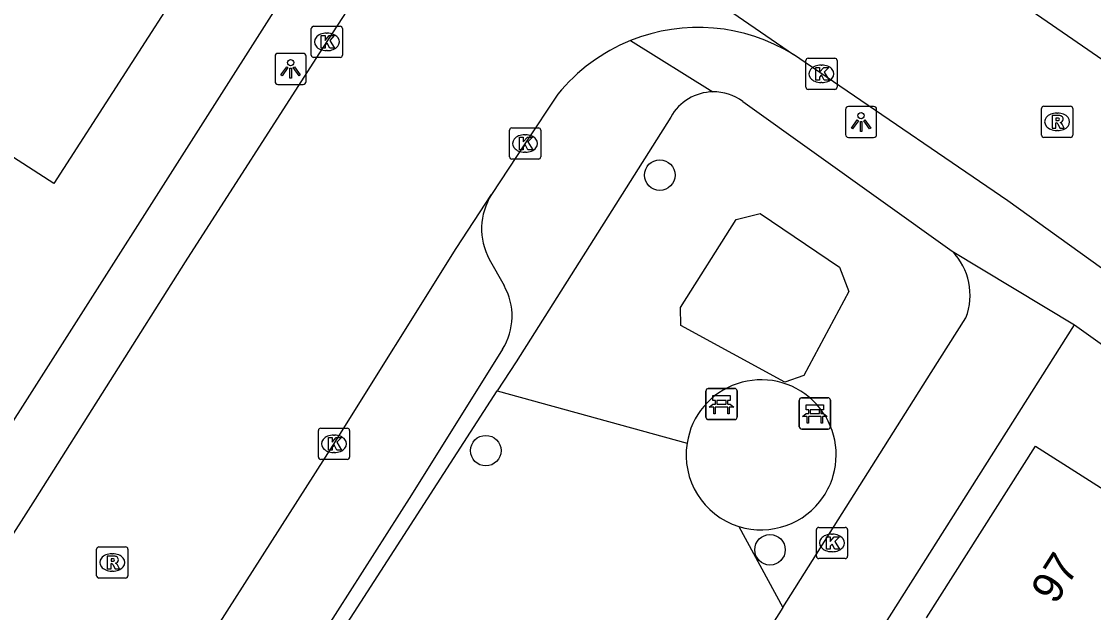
# Model space of a CAD drawing. Extents: x 159040 to 160094, y 381214 to 382518.
# Drawn here: x 159351.38 to 159385.76, y 381864.25 to 381883.21 of the extents above; entities that cross this region are included whole.
import ezdxf

# ---------------------------------------------------------------- set-up
doc = ezdxf.new("R2010")
doc.units = 0
for name, color, linetype in [('IMGEO_Bank', 7, 'Continuous'), ('IMGEO_Boom', 7, 'Continuous'), ('IMGEO_Groenvoorziening', 7, 'Continuous'), ('IMGEO_Kolk', 7, 'Continuous'), ('IMGEO_Lichtpunt', 7, 'Continuous'), ('IMGEO_Pand', 7, 'Continuous'), ('IMGEO_Pand_nummerreeks', 7, 'Continuous'), ('IMGEO_Rijbaan_lokaal_open', 7, 'Continuous'), ('IMGEO_Rioolput', 7, 'Continuous'), ('IMGEO_Voetpad_halfverhard', 7, 'Continuous'), ('IMGEO_Voetpad_open', 7, 'Continuous')]:
    doc.layers.add(name, color=color, linetype=linetype)

msp = doc.modelspace()

# ---------------------------------------------------------------- linework, layer by layer
at = {"layer": 'IMGEO_Bank'}
for p, q in [((159373.328, 381870.51), (159373.328, 381871.351)), ((159373.328, 381871.351), (159373.328, 381870.51)), ((159373.403, 381871.435), (159374.244, 381871.435)), ((159374.244, 381871.435), (159373.403, 381871.435)), ((159374.328, 381871.36), (159374.328, 381870.519)), ((159374.328, 381870.519), (159374.328, 381871.36)), ((159374.025, 381870.833), (159373.632, 381870.833)), ((159373.637, 381870.941), (159373.637, 381871.047)), ((159373.681, 381871.047), (159373.681, 381870.941)), ((159373.969, 381871.053), (159373.687, 381871.053)), ((159373.687, 381870.935), (159373.969, 381870.935)), ((159373.975, 381870.941), (159373.975, 381871.047)), ((159374.019, 381871.047), (159374.019, 381870.941)), ((159376.32, 381870.209), (159376.32, 381871.05)), ((159376.32, 381871.05), (159376.32, 381870.209)), ((159376.395, 381871.134), (159377.236, 381871.134)), ((159377.236, 381871.134), (159376.395, 381871.134)), ((159377.32, 381871.059), (159377.32, 381870.218)), ((159377.32, 381870.218), (159377.32, 381871.059)), ((159377.017, 381870.532), (159376.624, 381870.532)), ((159376.629, 381870.64), (159376.629, 381870.746)), ((159376.673, 381870.746), (159376.673, 381870.64)), ((159376.961, 381870.752), (159376.679, 381870.752)), ((159376.679, 381870.634), (159376.961, 381870.634)), ((159376.967, 381870.64), (159376.967, 381870.746)), ((159377.011, 381870.746), (159377.011, 381870.64)), ((159374.253, 381870.435), (159373.412, 381870.435)), ((159373.412, 381870.435), (159374.253, 381870.435)), ((159377.245, 381870.134), (159376.404, 381870.134)), ((159376.404, 381870.134), (159377.245, 381870.134))]:
    msp.add_line(p, q, dxfattribs=at)
for points in [[(159373.631, 381871.053), (159373.545, 381871.053), (159373.545, 381871.214), (159374.108, 381871.214), (159374.108, 381871.053), (159374.025, 381871.053)], [(159373.575, 381870.833), (159373.433, 381870.833), (159373.545, 381870.935), (159373.631, 381870.935)], [(159373.625, 381870.826), (159373.625, 381870.619), (159373.582, 381870.619), (159373.582, 381870.826)], [(159374.025, 381870.935), (159374.108, 381870.935), (159374.22, 381870.833), (159374.081, 381870.833)], [(159374.075, 381870.826), (159374.075, 381870.619), (159374.031, 381870.619), (159374.031, 381870.826)], [(159376.623, 381870.752), (159376.537, 381870.752), (159376.537, 381870.913), (159377.1, 381870.913), (159377.1, 381870.752), (159377.017, 381870.752)], [(159376.567, 381870.532), (159376.425, 381870.532), (159376.537, 381870.634), (159376.623, 381870.634)], [(159376.617, 381870.525), (159376.617, 381870.318), (159376.574, 381870.318), (159376.574, 381870.525)], [(159377.017, 381870.634), (159377.1, 381870.634), (159377.212, 381870.532), (159377.073, 381870.532)], [(159377.067, 381870.525), (159377.067, 381870.318), (159377.023, 381870.318), (159377.023, 381870.525)]]:
    msp.add_lwpolyline(points, dxfattribs=at)
for centre, radius, start, end in [((159373.406, 381871.357), 0.0779, 92.4484, 184.2845), ((159373.406, 381871.357), 0.0779, 92.4484, 184.2845), ((159374.25, 381871.357), 0.0779, 2.4484, 94.2845), ((159374.25, 381871.357), 0.0779, 2.4484, 94.2845), ((159373.575, 381870.826), 0.00671, 2.8957, 87.1043), ((159373.632, 381870.826), 0.00671, 92.8957, 177.1043), ((159373.63, 381871.046), 0.00671, 2.8957, 87.1043), ((159373.63, 381870.942), 0.00671, 272.8957, 357.1043), ((159373.687, 381871.046), 0.00671, 92.8957, 177.1043), ((159373.687, 381870.942), 0.00671, 182.8957, 267.1043), ((159373.969, 381871.046), 0.00671, 2.8957, 87.1043), ((159373.969, 381870.942), 0.00671, 272.8957, 357.1043), ((159374.026, 381871.046), 0.00671, 92.8957, 177.1043), ((159374.026, 381870.942), 0.00671, 182.8957, 267.1043), ((159374.024, 381870.826), 0.00671, 2.8957, 87.1043), ((159374.081, 381870.826), 0.00671, 92.8957, 177.1043), ((159376.398, 381871.056), 0.0779, 92.4484, 184.2845), ((159376.398, 381871.056), 0.0779, 92.4484, 184.2845), ((159377.242, 381871.056), 0.0779, 2.4484, 94.2845), ((159377.242, 381871.056), 0.0779, 2.4484, 94.2845), ((159373.406, 381870.513), 0.0779, 182.4484, 274.2845), ((159373.406, 381870.513), 0.0779, 182.4484, 274.2845), ((159374.25, 381870.513), 0.0779, 272.4484, 4.2845), ((159374.25, 381870.513), 0.0779, 272.4484, 4.2845), ((159376.567, 381870.525), 0.00671, 2.8957, 87.1043), ((159376.624, 381870.525), 0.00671, 92.8957, 177.1043), ((159376.622, 381870.745), 0.00671, 2.8957, 87.1043), ((159376.622, 381870.641), 0.00671, 272.8957, 357.1043), ((159376.679, 381870.745), 0.00671, 92.8957, 177.1043), ((159376.679, 381870.641), 0.00671, 182.8957, 267.1043), ((159376.961, 381870.745), 0.00671, 2.8957, 87.1043), ((159376.961, 381870.641), 0.00671, 272.8957, 357.1043), ((159377.018, 381870.745), 0.00671, 92.8957, 177.1043), ((159377.018, 381870.641), 0.00671, 182.8957, 267.1043), ((159377.016, 381870.525), 0.00671, 2.8957, 87.1043), ((159377.073, 381870.525), 0.00671, 92.8957, 177.1043), ((159376.398, 381870.212), 0.0779, 182.4484, 274.2845), ((159376.398, 381870.212), 0.0779, 182.4484, 274.2845), ((159377.242, 381870.212), 0.0779, 272.4484, 4.2845), ((159377.242, 381870.212), 0.0779, 272.4484, 4.2845)]:
    msp.add_arc(centre, radius, start, end, dxfattribs=at)
at = {"layer": 'IMGEO_Boom'}
for centre in [(159371.847, 381878.277), (159366.267, 381869.441), (159375.382, 381866.261)]:
    msp.add_circle(centre, 0.489, dxfattribs=at)
at = {"layer": 'IMGEO_Groenvoorziening'}
for points in [[(159366.633, 381871.354), (159372.721, 381869.68)], [(159374.378, 381867.01), (159375.795, 381864.415)]]:
    msp.add_lwpolyline(points, dxfattribs=at)
at = {"layer": 'IMGEO_Kolk'}
for p, q in [((159360.671, 381882.123), (159360.671, 381882.975)), ((159360.746, 381883.049), (159361.598, 381883.049)), ((159361.672, 381882.975), (159361.672, 381882.123)), ((159361.159, 381882.829), (159361.184, 381882.829)), ((159361.182, 381882.269), (159361.157, 381882.269)), ((159361.598, 381882.049), (159360.746, 381882.049)), ((159376.531, 381881.1), (159376.531, 381881.952)), ((159376.606, 381882.026), (159377.458, 381882.026)), ((159377.532, 381881.952), (159377.532, 381881.1)), ((159377.019, 381881.806), (159377.044, 381881.806)), ((159377.042, 381881.246), (159377.017, 381881.246)), ((159377.458, 381881.026), (159376.606, 381881.026)), ((159367.102, 381879.791), (159367.954, 381879.791)), ((159367.027, 381878.865), (159367.027, 381879.717)), ((159367.515, 381879.571), (159367.54, 381879.571)), ((159368.028, 381879.717), (159368.028, 381878.865)), ((159367.954, 381878.791), (159367.102, 381878.791)), ((159367.538, 381879.011), (159367.513, 381879.011)), ((159360.974, 381870.159), (159361.826, 381870.159)), ((159360.899, 381869.233), (159360.899, 381870.085)), ((159361.387, 381869.939), (159361.412, 381869.939)), ((159361.9, 381870.085), (159361.9, 381869.233)), ((159361.826, 381869.159), (159360.974, 381869.159)), ((159361.41, 381869.379), (159361.385, 381869.379)), ((159376.871, 381866.054), (159376.871, 381866.906)), ((159376.946, 381866.98), (159377.798, 381866.98)), ((159377.359, 381866.76), (159377.384, 381866.76)), ((159377.872, 381866.906), (159377.872, 381866.054)), ((159377.382, 381866.2), (159377.357, 381866.2)), ((159377.798, 381865.98), (159376.946, 381865.98))]:
    msp.add_line(p, q, dxfattribs=at)
for points in [[(159360.671, 381882.123), (159360.671, 381882.975)], [(159360.746, 381883.049), (159361.598, 381883.049)], [(159361.672, 381882.975), (159361.672, 381882.123)], [(159360.992, 381882.749), (159361.115, 381882.749), (159361.115, 381882.598), (159361.245, 381882.749), (159361.409, 381882.749), (159361.263, 381882.598), (159361.416, 381882.349), (159361.264, 381882.349), (159361.179, 381882.513), (159361.115, 381882.446), (159361.115, 381882.349), (159360.992, 381882.349), (159360.992, 381882.749)], [(159361.598, 381882.049), (159360.746, 381882.049)], [(159376.531, 381881.1), (159376.531, 381881.952)], [(159376.606, 381882.026), (159377.458, 381882.026)], [(159377.532, 381881.952), (159377.532, 381881.1)], [(159376.852, 381881.726), (159376.975, 381881.726), (159376.975, 381881.575), (159377.105, 381881.726), (159377.269, 381881.726), (159377.123, 381881.575), (159377.276, 381881.326), (159377.124, 381881.326), (159377.039, 381881.49), (159376.975, 381881.423), (159376.975, 381881.326), (159376.852, 381881.326), (159376.852, 381881.726)], [(159377.458, 381881.026), (159376.606, 381881.026)], [(159367.102, 381879.791), (159367.954, 381879.791)], [(159367.027, 381878.865), (159367.027, 381879.717)], [(159367.348, 381879.491), (159367.471, 381879.491), (159367.471, 381879.34), (159367.601, 381879.491), (159367.765, 381879.491), (159367.619, 381879.34), (159367.772, 381879.091), (159367.62, 381879.091), (159367.535, 381879.255), (159367.471, 381879.188), (159367.471, 381879.091), (159367.348, 381879.091), (159367.348, 381879.491)], [(159368.028, 381879.717), (159368.028, 381878.865)], [(159367.954, 381878.791), (159367.102, 381878.791)], [(159360.974, 381870.159), (159361.826, 381870.159)], [(159360.899, 381869.233), (159360.899, 381870.085)], [(159361.22, 381869.859), (159361.343, 381869.859), (159361.343, 381869.708), (159361.473, 381869.859), (159361.637, 381869.859), (159361.491, 381869.708), (159361.644, 381869.459), (159361.492, 381869.459), (159361.407, 381869.623), (159361.343, 381869.556), (159361.343, 381869.459), (159361.22, 381869.459), (159361.22, 381869.859)], [(159361.9, 381870.085), (159361.9, 381869.233)], [(159361.826, 381869.159), (159360.974, 381869.159)], [(159376.871, 381866.054), (159376.871, 381866.906)], [(159376.946, 381866.98), (159377.798, 381866.98)], [(159377.872, 381866.906), (159377.872, 381866.054)], [(159377.192, 381866.68), (159377.315, 381866.68), (159377.315, 381866.529), (159377.445, 381866.68), (159377.609, 381866.68), (159377.463, 381866.529), (159377.616, 381866.28), (159377.464, 381866.28), (159377.379, 381866.444), (159377.315, 381866.377), (159377.315, 381866.28), (159377.192, 381866.28), (159377.192, 381866.68)], [(159377.798, 381865.98), (159376.946, 381865.98)]]:
    msp.add_lwpolyline(points, dxfattribs=at)
for centre, start, end in [((159360.748, 381882.973), 91.552, 178.448), ((159360.748, 381882.973), 91.552, 178.448), ((159361.596, 381882.973), 1.552, 88.448), ((159361.596, 381882.973), 1.552, 88.448), ((159360.748, 381882.125), 181.552, 268.448), ((159360.748, 381882.125), 181.552, 268.448), ((159361.596, 381882.125), 271.552, 358.448), ((159361.596, 381882.125), 271.552, 358.448), ((159376.608, 381881.95), 91.552, 178.448), ((159376.608, 381881.95), 91.552, 178.448), ((159377.456, 381881.95), 1.552, 88.448), ((159377.456, 381881.95), 1.552, 88.448), ((159376.608, 381881.102), 181.552, 268.448), ((159376.608, 381881.102), 181.552, 268.448), ((159377.456, 381881.102), 271.552, 358.448), ((159377.456, 381881.102), 271.552, 358.448), ((159367.104, 381879.715), 91.552, 178.448), ((159367.104, 381879.715), 91.552, 178.448), ((159367.952, 381879.715), 1.552, 88.448), ((159367.952, 381879.715), 1.552, 88.448), ((159367.104, 381878.867), 181.552, 268.448), ((159367.104, 381878.867), 181.552, 268.448), ((159367.952, 381878.867), 271.552, 358.448), ((159367.952, 381878.867), 271.552, 358.448), ((159360.976, 381870.083), 91.552, 178.448), ((159360.976, 381870.083), 91.552, 178.448), ((159361.824, 381870.083), 1.552, 88.448), ((159361.824, 381870.083), 1.552, 88.448), ((159360.976, 381869.235), 181.552, 268.448), ((159360.976, 381869.235), 181.552, 268.448), ((159361.824, 381869.235), 271.552, 358.448), ((159361.824, 381869.235), 271.552, 358.448), ((159376.948, 381866.904), 91.552, 178.448), ((159376.948, 381866.904), 91.552, 178.448), ((159377.796, 381866.904), 1.552, 88.448), ((159377.796, 381866.904), 1.552, 88.448), ((159376.948, 381866.056), 181.552, 268.448), ((159376.948, 381866.056), 181.552, 268.448), ((159377.796, 381866.056), 271.552, 358.448), ((159377.796, 381866.056), 271.552, 358.448)]:
    msp.add_arc(centre, 0.0765, start, end, dxfattribs=at)
for centre, major_axis, ratio, start_param, end_param in [((159361.158, 381882.549), (-0.387, 0.002), 0.722429, 4.712389, 7.853982), ((159361.183, 381882.549), (-0.39, 0.002), 0.717154, 1.570796, 4.712389), ((159377.018, 381881.526), (-0.387, 0.002), 0.722429, 4.712389, 7.853982), ((159377.043, 381881.526), (-0.39, 0.002), 0.717154, 1.570796, 4.712389), ((159367.514, 381879.291), (-0.387, 0.002), 0.722429, 4.712389, 7.853982), ((159367.539, 381879.291), (-0.39, 0.002), 0.717154, 1.570796, 4.712389), ((159361.386, 381869.659), (-0.387, 0.002), 0.722429, 4.712389, 7.853982), ((159361.411, 381869.659), (-0.39, 0.002), 0.717154, 1.570796, 4.712389), ((159377.358, 381866.48), (-0.387, 0.002), 0.722429, 4.712389, 7.853982), ((159377.383, 381866.48), (-0.39, 0.002), 0.717154, 1.570796, 4.712389)]:
    msp.add_ellipse(centre, major_axis=major_axis, ratio=ratio, start_param=start_param, end_param=end_param, dxfattribs=at)
at = {"layer": 'IMGEO_Lichtpunt'}
for p, q in [((159360.41, 381882.182), (159359.602, 381882.182)), ((159360.41, 381882.182), (159359.602, 381882.182)), ((159359.508, 381882.087), (159359.508, 381881.28)), ((159359.508, 381882.087), (159359.508, 381881.28)), ((159360.504, 381881.28), (159360.504, 381882.087)), ((159360.504, 381881.28), (159360.504, 381882.087)), ((159359.602, 381881.186), (159360.41, 381881.186)), ((159359.602, 381881.186), (159360.41, 381881.186)), ((159378.707, 381880.479), (159377.899, 381880.479)), ((159378.707, 381880.479), (159377.899, 381880.479)), ((159377.805, 381880.384), (159377.805, 381879.577)), ((159377.805, 381880.384), (159377.805, 381879.577)), ((159378.801, 381879.577), (159378.801, 381880.384)), ((159378.801, 381879.577), (159378.801, 381880.384)), ((159377.899, 381879.483), (159378.707, 381879.483)), ((159377.899, 381879.483), (159378.707, 381879.483))]:
    msp.add_line(p, q, dxfattribs=at)
for points in [[(159359.882, 381881.751), (159359.921, 381881.723), (159359.733, 381881.461), (159359.695, 381881.488), (159359.882, 381881.751)], [(159359.984, 381881.703), (159360.031, 381881.703), (159360.031, 381881.381), (159359.984, 381881.381), (159359.984, 381881.703)], [(159360.094, 381881.723), (159360.132, 381881.75), (159360.319, 381881.488), (159360.28, 381881.46), (159360.094, 381881.723)], [(159378.179, 381880.048), (159378.218, 381880.02), (159378.03, 381879.758), (159377.992, 381879.785), (159378.179, 381880.048)], [(159378.281, 381880), (159378.328, 381880), (159378.328, 381879.678), (159378.281, 381879.678), (159378.281, 381880)], [(159378.391, 381880.02), (159378.429, 381880.047), (159378.616, 381879.785), (159378.577, 381879.757), (159378.391, 381880.02)]]:
    msp.add_lwpolyline(points, dxfattribs=at)
for centre in [(159360.007, 381881.885), (159378.304, 381880.182)]:
    msp.add_circle(centre, 0.0994, dxfattribs=at)
for centre, start, end in [((159359.602, 381882.087), 90, 180), ((159359.602, 381882.087), 90, 180), ((159360.41, 381882.087), 0, 90), ((159360.41, 381882.087), 0, 90), ((159359.602, 381881.28), 180, 270), ((159359.602, 381881.28), 180, 270), ((159360.41, 381881.28), 270, 0), ((159360.41, 381881.28), 270, 360), ((159377.899, 381880.384), 90, 180), ((159377.899, 381880.384), 90, 180), ((159378.707, 381880.384), 0, 90), ((159378.707, 381880.384), 0, 90), ((159377.899, 381879.577), 180, 270), ((159377.899, 381879.577), 180, 270), ((159378.707, 381879.577), 270, 0), ((159378.707, 381879.577), 270, 360)]:
    msp.add_arc(centre, 0.0946, start, end, dxfattribs=at)
at = {"layer": 'IMGEO_Pand'}
for points in [[(159351.372, 381888.315), (159356.797, 381884.82), (159352.409, 381878.007), (159346.983, 381881.502)], [(159380.405, 381864.08), (159383.895, 381869.579), (159391.026, 381865.053), (159388.347, 381860.832), (159387.536, 381859.554)]]:
    msp.add_lwpolyline(points, dxfattribs=at)
at = {"layer": 'IMGEO_Rijbaan_lokaal_open'}
for points in [[(159356.898, 381904.755), (159359.228, 381902.824), (159361.803, 381900.713), (159364.908, 381898.01), (159368.906, 381894.441), (159371.682, 381891.995), (159372.607, 381891.419), (159374.914, 381889.793), (159378.123, 381887.473), (159378.766, 381887.027), (159382.491, 381884.442), (159394.639, 381876.061), (159401.266, 381871.522), (159409.164, 381865.996), (159418.724, 381859.338), (159420.402, 381857.938), (159424.695, 381854.911)], [(159362.316, 381891.65), (159376.136, 381882.142)], [(159336.942, 381844.497), (159338.933, 381847.625), (159344.796, 381856.852), (159346.625, 381859.725), (159351.829, 381867.879), (159356.637, 381875.498), (159360.926, 381882.168), (159362.58, 381884.718)], [(159421.598, 381850.302), (159417.059, 381853.43), (159413.89, 381855.955), (159406.023, 381861.421), (159397.966, 381866.975), (159388.94, 381873.188), (159383.005, 381877.455), (159377.184, 381881.424), (159376.136, 381882.142)], [(159368.58, 381880.87), (159367.537, 381879.308), (159366.451, 381877.655)], [(159338.189, 381833.159), (159342.307, 381839.702), (159347.915, 381848.544), (159353.758, 381857.696), (159361.37, 381869.614), (159365.312, 381875.921), (159366.451, 381877.655)]]:
    msp.add_lwpolyline(points, dxfattribs=at)
for centre, radius, start, end in [((159373.079, 381877.215), 5.799, 58.1849, 111.9995), ((159373.089, 381877.206), 5.81, 112.0631, 140.9086)]:
    msp.add_arc(centre, radius, start, end, dxfattribs=at)
at = {"layer": 'IMGEO_Rioolput'}
for p, q in [((159384.166, 381880.487), (159385.018, 381880.487)), ((159384.091, 381879.561), (159384.091, 381880.413)), ((159384.579, 381880.267), (159384.604, 381880.267)), ((159385.092, 381880.413), (159385.092, 381879.561)), ((159385.018, 381879.487), (159384.166, 381879.487)), ((159384.602, 381879.707), (159384.577, 381879.707)), ((159353.862, 381866.355), (159354.714, 381866.355)), ((159353.787, 381865.429), (159353.787, 381866.281)), ((159354.275, 381866.135), (159354.3, 381866.135)), ((159354.788, 381866.281), (159354.788, 381865.429)), ((159354.714, 381865.355), (159353.862, 381865.355)), ((159354.298, 381865.575), (159354.273, 381865.575))]:
    msp.add_line(p, q, dxfattribs=at)
for points in [[(159384.166, 381880.487), (159385.018, 381880.487)], [(159384.091, 381879.561), (159384.091, 381880.413)], [(159384.68, 381880.185), (159384.428, 381880.187), (159384.428, 381879.787)], [(159384.606, 381880.106), (159384.552, 381880.106), (159384.552, 381880.025)], [(159385.092, 381880.413), (159385.092, 381879.561)], [(159384.428, 381879.787), (159384.552, 381879.787), (159384.552, 381879.949), (159384.563, 381879.949)], [(159384.552, 381880.025), (159384.604, 381880.025)], [(159384.61, 381879.92), (159384.681, 381879.787), (159384.821, 381879.787), (159384.756, 381879.913)], [(159385.018, 381879.487), (159384.166, 381879.487)], [(159353.862, 381866.355), (159354.714, 381866.355)], [(159353.787, 381865.429), (159353.787, 381866.281)], [(159354.376, 381866.053), (159354.124, 381866.055), (159354.124, 381865.655)], [(159354.788, 381866.281), (159354.788, 381865.429)], [(159354.124, 381865.655), (159354.248, 381865.655), (159354.248, 381865.817), (159354.259, 381865.817)], [(159354.302, 381865.974), (159354.248, 381865.974), (159354.248, 381865.893)], [(159354.248, 381865.893), (159354.3, 381865.893)], [(159354.306, 381865.788), (159354.377, 381865.655), (159354.517, 381865.655), (159354.452, 381865.781)], [(159354.714, 381865.355), (159353.862, 381865.355)]]:
    msp.add_lwpolyline(points, dxfattribs=at)
for centre, radius, start, end in [((159384.168, 381880.411), 0.0765, 91.552, 178.448), ((159384.168, 381880.411), 0.0765, 91.552, 178.448), ((159385.016, 381880.411), 0.0765, 1.552, 88.448), ((159385.016, 381880.411), 0.0765, 1.552, 88.448), ((159384.612, 381880.01), 0.0964, 77.0061, 93.1865), ((159384.626, 381880.067), 0.0378, 276.6634, 79.6772), ((159384.679, 381880.075), 0.109, 350.3612, 89.416), ((159384.562, 381879.896), 0.0533, 26.0293, 88.6989), ((159384.588, 381880.214), 0.19, 274.7715, 282.9687), ((159384.677, 381880.075), 0.112, 277.5842, 350.9817), ((159384.661, 381879.86), 0.108, 29.5134, 73.7905), ((159384.168, 381879.563), 0.0765, 181.552, 268.448), ((159384.168, 381879.563), 0.0765, 181.552, 268.448), ((159385.016, 381879.563), 0.0765, 271.552, 358.448), ((159385.016, 381879.563), 0.0765, 271.552, 358.448), ((159353.864, 381866.279), 0.0765, 91.552, 178.448), ((159353.864, 381866.279), 0.0765, 91.552, 178.448), ((159354.712, 381866.279), 0.0765, 1.552, 88.448), ((159354.712, 381866.279), 0.0765, 1.552, 88.448), ((159354.375, 381865.943), 0.109, 350.3612, 89.416), ((159354.258, 381865.764), 0.0533, 26.0293, 88.6989), ((159354.284, 381866.082), 0.19, 274.7715, 282.9687), ((159354.308, 381865.878), 0.0964, 77.0061, 93.1865), ((159354.322, 381865.935), 0.0378, 276.6634, 79.6772), ((159354.373, 381865.943), 0.112, 277.5842, 350.9817), ((159354.357, 381865.728), 0.108, 29.5134, 73.7905), ((159353.864, 381865.431), 0.0765, 181.552, 268.448), ((159353.864, 381865.431), 0.0765, 181.552, 268.448), ((159354.712, 381865.431), 0.0765, 271.552, 358.448), ((159354.712, 381865.431), 0.0765, 271.552, 358.448)]:
    msp.add_arc(centre, radius, start, end, dxfattribs=at)
for centre, major_axis, ratio, start_param, end_param in [((159384.578, 381879.987), (-0.387, 0.002), 0.722429, 4.712389, 7.853982), ((159384.603, 381879.987), (-0.39, 0.002), 0.717154, 1.570796, 4.712389), ((159354.274, 381865.855), (-0.387, 0.002), 0.722429, 4.712389, 7.853982), ((159354.299, 381865.855), (-0.39, 0.002), 0.717154, 1.570796, 4.712389)]:
    msp.add_ellipse(centre, major_axis=major_axis, ratio=ratio, start_param=start_param, end_param=end_param, dxfattribs=at)
at = {"layer": 'IMGEO_Voetpad_halfverhard'}
msp.add_lwpolyline([(159377.606, 381875.321), (159377.907, 381874.539), (159376.47, 381871.851), (159375.858, 381871.638), (159372.524, 381873.451), (159372.509, 381874.026), (159374.292, 381876.849), (159375.062, 381877.046), (159377.606, 381875.321)], dxfattribs=at)
for centre, radius, start, end in [((159375.098, 381869.306), 2.406, 343.9624, 171.055), ((159375.099, 381869.307), 2.407, 171.0811, 252.5663), ((159375.084, 381869.312), 2.422, 326.3517, 343.9141), ((159375.098, 381869.308), 2.408, 252.6019, 326.2518)]:
    msp.add_arc(centre, radius, start, end, dxfattribs=at)
at = {"layer": 'IMGEO_Voetpad_open'}
for points in [[(159360.21, 381884.703), (159349.432, 381867.776)], [(159370.907, 381882.591), (159373.553, 381880.947)], [(159374.506, 381880.639), (159381.223, 381875.841)], [(159372.198, 381880.139), (159367.239, 381872.292), (159366.633, 381871.354)], [(159381.223, 381875.841), (159385.148, 381873.477)], [(159366.38, 381875.576), (159366.853, 381874.735)], [(159375.795, 381864.415), (159380.556, 381871.945), (159381.665, 381873.699)], [(159352.77, 381822.367), (159385.148, 381873.477)], [(159385.148, 381873.477), (159401.551, 381861.756)], [(159366.807, 381872.694), (159363.887, 381868.023), (159350.427, 381846.945), (159344.824, 381838.112), (159342.881, 381835.025)], [(159358.302, 381858.425), (159358.524, 381858.795), (159366.633, 381871.354)], [(159375.795, 381864.415), (159368.38, 381852.687), (159367.724, 381851.534)]]:
    msp.add_lwpolyline(points, dxfattribs=at)
for centre, radius, start, end in [((159373.569, 381879.38), 1.567, 90.5826, 151.0335), ((159373.572, 381879.378), 1.569, 53.4767, 90.7027), ((159368.194, 381876.555), 2.061, 147.7395, 208.3486), ((159379.768, 381874.424), 2.031, 339.0817, 44.2369), ((159365.11, 381873.753), 2, 328.0225, 29.3953)]:
    msp.add_arc(centre, radius, start, end, dxfattribs=at)

# ---------------------------------------------------------------- texts
at = {"layer": 'IMGEO_Pand_nummerreeks'}
msp.add_text('97', height=1, rotation=57.599, dxfattribs=at).set_placement((159384.538, 381864.472))

doc.saveas('drawing.dxf')
